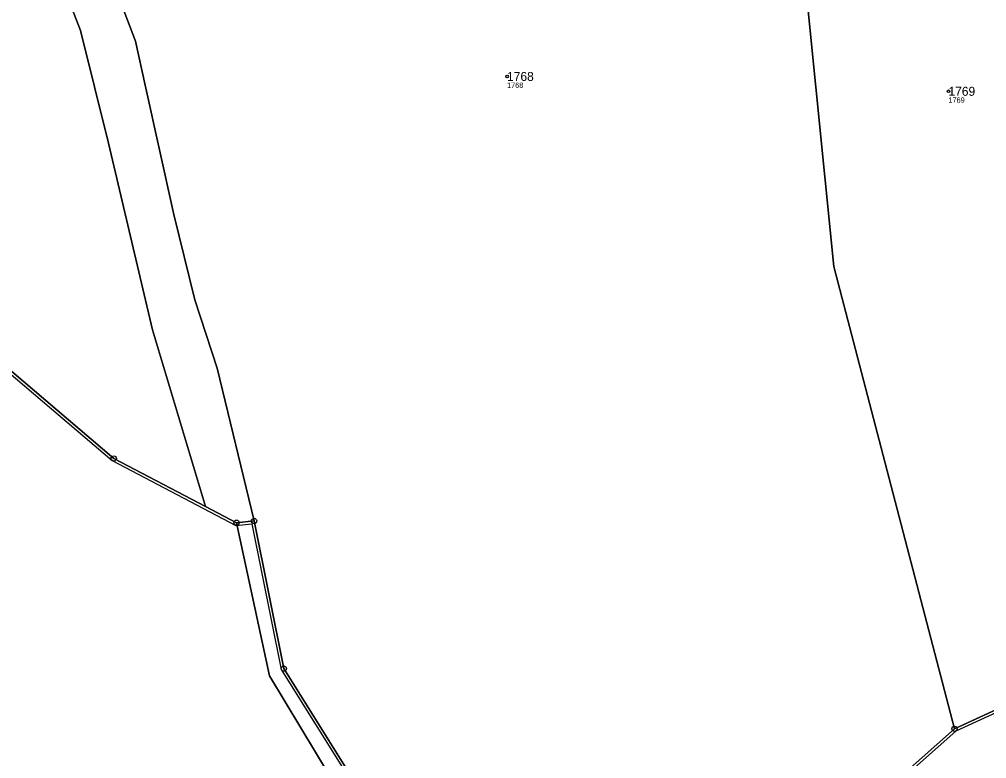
# Model space of a CAD drawing. Extents: x -770088 to -765625, y -1057899 to -1053934.
# Drawn here: x -767729.4 to -767546.4, y -1055752.9 to -1055612.9 of the extents above; entities that cross this region are included whole.
import ezdxf

# ---------------------------------------------------------------- set-up
doc = ezdxf.new("R2010")
doc.units = 0
for name, color, linetype in [('Definiční body', 7, 'Continuous'), ('Hranice parcel', 7, 'Continuous'), ('Parcelní čísla', 7, 'Continuous'), ('Polygon parcely', 7, 'Continuous'), ('Vnitřní kresba', 7, 'Continuous'), ('Značky bodu BP', 7, 'Continuous')]:
    doc.layers.add(name, color=color, linetype=linetype)

msp = doc.modelspace()

# ---------------------------------------------------------------- linework, layer by layer
at = {"layer": 'Definiční body'}
for centre in [(-767637.15, -1055623.73), (-767553.65, -1055626.54)]:
    msp.add_circle(centre, 0.25, dxfattribs=at)
at = {"layer": 'Hranice parcel'}
for p, q in [((-767694.2, -1055705.14), (-767688.33, -1055708.21)), ((-767688.33, -1055708.21), (-767685.01, -1055707.88)), ((-767552.51, -1055747.23), (-767526.88, -1055735.47))]:
    msp.add_line(p, q, dxfattribs=at)
for points in [[(-767685.01, -1055707.88), (-767692, -1055678.93), (-767696.21, -1055666.01), (-767700.19, -1055649.85), (-767705.63, -1055625.36), (-767707.42, -1055617.04), (-767716.16, -1055594.17), (-767721.17, -1055581.35), (-767730.22, -1055558.23), (-767733.29, -1055543.04), (-767733.19, -1055525.38), (-767730.55, -1055514.39), (-767726.52, -1055509.04), (-767726.49, -1055503.44)], [(-767694.2, -1055705.14), (-767704.24, -1055671.7), (-767712.56, -1055636.33), (-767717.83, -1055615.02), (-767726.52, -1055592.58), (-767741.87, -1055564), (-767746.66, -1055553.56), (-767747.75, -1055549.17), (-767748.22, -1055543.05), (-767746.48, -1055522.16), (-767747.15, -1055505.65)], [(-767552.51, -1055747.23), (-767575.32, -1055659.71), (-767588.91, -1055524.49)], [(-767983.52, -1055552.84), (-767912.57, -1055567.84), (-767860.83, -1055579.25), (-767844.82, -1055586.75), (-767796.24, -1055618.55), (-767763.05, -1055652.16), (-767711.56, -1055696.05), (-767694.2, -1055705.14)], [(-767391.2, -1056169.09), (-767417.3, -1056105.71), (-767429.7, -1056093.99), (-767435.73, -1056084.7), (-767495.32, -1056050.14), (-767533.97, -1056040.27), (-767559.59, -1056004.47), (-767572.95, -1055975.44), (-767598.42, -1055931.17), (-767621.41, -1055888.84), (-767634.7, -1055844.52), (-767634.6, -1055821.05), (-767640.38, -1055801.4), (-767667.3, -1055761.84), (-767682.06, -1055737.19), (-767688.33, -1055708.21)], [(-767685.01, -1055707.88), (-767679.38, -1055735.84), (-767665.18, -1055758.55)], [(-767665.18, -1055758.55), (-767656.43, -1055759.95), (-767649.19, -1055772.72), (-767625.46, -1055774.82), (-767583.98, -1055768.27), (-767574.79, -1055766.98), (-767552.51, -1055747.23)]]:
    msp.add_lwpolyline(points, dxfattribs=at)
at = {"layer": 'Polygon parcely'}
for points in [[(-767574.79, -1055766.98), (-767552.51, -1055747.23), (-767575.32, -1055659.71), (-767588.91, -1055524.49), (-767590.45, -1055515.54), (-767624.3, -1055512.63), (-767660.15, -1055509.27), (-767701.59, -1055505.63), (-767726.49, -1055503.44), (-767726.52, -1055509.04), (-767730.55, -1055514.39), (-767733.19, -1055525.38), (-767733.29, -1055543.04), (-767730.22, -1055558.23), (-767721.17, -1055581.35), (-767716.16, -1055594.17), (-767707.42, -1055617.04), (-767705.63, -1055625.36), (-767700.19, -1055649.85), (-767696.21, -1055666.01), (-767692, -1055678.93), (-767685.01, -1055707.88), (-767679.38, -1055735.84), (-767665.18, -1055758.55)], [(-767667.3, -1055761.84), (-767682.06, -1055737.19), (-767688.33, -1055708.21), (-767694.2, -1055705.14), (-767711.56, -1055696.05), (-767763.05, -1055652.16), (-767796.24, -1055618.55), (-767844.82, -1055586.75), (-767860.83, -1055579.25), (-767912.57, -1055567.84), (-767983.52, -1055552.84), (-768086.16, -1055607.62)], [(-767741.87, -1055564), (-767726.52, -1055592.58), (-767717.83, -1055615.02), (-767712.56, -1055636.33), (-767704.24, -1055671.7), (-767694.2, -1055705.14), (-767688.33, -1055708.21), (-767685.01, -1055707.88), (-767692, -1055678.93), (-767696.21, -1055666.01), (-767700.19, -1055649.85), (-767705.63, -1055625.36), (-767707.42, -1055617.04), (-767716.16, -1055594.17), (-767721.17, -1055581.35), (-767730.22, -1055558.23)], [(-767763.05, -1055652.16), (-767711.56, -1055696.05), (-767694.2, -1055705.14), (-767704.24, -1055671.7), (-767712.56, -1055636.33), (-767717.83, -1055615.02), (-767726.52, -1055592.58), (-767741.87, -1055564)], [(-767455.85, -1055702.9), (-767491.49, -1055719.24), (-767492.49, -1055719.7), (-767525.93, -1055735.04), (-767526.88, -1055735.47), (-767552.51, -1055747.23), (-767574.79, -1055766.98)], [(-767685.01, -1055707.88), (-767688.33, -1055708.21), (-767682.06, -1055737.19), (-767667.3, -1055761.84), (-767640.38, -1055801.4), (-767634.6, -1055821.05), (-767634.7, -1055844.52), (-767621.41, -1055888.84), (-767598.42, -1055931.17), (-767572.95, -1055975.44), (-767559.59, -1056004.47), (-767533.97, -1056040.27), (-767495.32, -1056050.14), (-767435.73, -1056084.7), (-767429.7, -1056093.99), (-767417.3, -1056105.71), (-767391.2, -1056169.09)], [(-767569.23, -1055975.4), (-767595.65, -1055929.32), (-767618.1, -1055887.25), (-767630.79, -1055844.75), (-767631.37, -1055821.28), (-767637.99, -1055797.7), (-767665.18, -1055758.55), (-767679.38, -1055735.84), (-767685.01, -1055707.88)]]:
    msp.add_lwpolyline(points, dxfattribs=at)
msp.add_lwpolyline([(-767532.63, -1055628.1), (-767538.38, -1055520.72), (-767588.91, -1055524.49), (-767575.32, -1055659.71), (-767552.51, -1055747.23), (-767526.88, -1055735.47)], close=True, dxfattribs=at)
at = {"layer": 'Vnitřní kresba'}
for p, q in [((-767763.41, -1055652.51), (-767711.83, -1055696.47)), ((-767711.83, -1055696.47), (-767688.43, -1055708.72)), ((-767455.67, -1055703.37), (-767552.25, -1055747.66)), ((-767688.43, -1055708.72), (-767685.41, -1055708.42)), ((-767685.41, -1055708.42), (-767679.85, -1055736.03)), ((-767679.85, -1055736.03), (-767665.48, -1055759.01)), ((-767574.57, -1055767.45), (-767552.25, -1055747.66))]:
    msp.add_line(p, q, dxfattribs=at)
at = {"layer": 'Značky bodu BP'}
for centre, radius in [((-767711.56, -1055696.05), 0.5), ((-767711.56, -1055696.05), 0.0303), ((-767688.33, -1055708.21), 0.5), ((-767688.33, -1055708.21), 0.0303), ((-767685.01, -1055707.88), 0.5), ((-767685.01, -1055707.88), 0.0303), ((-767679.38, -1055735.84), 0.5), ((-767679.38, -1055735.84), 0.0303), ((-767552.51, -1055747.23), 0.5), ((-767552.51, -1055747.23), 0.0303)]:
    msp.add_circle(centre, radius, dxfattribs=at)

# ---------------------------------------------------------------- texts
at = {"layer": 'Definiční body'}
for s, p in [('1768', (-767637.15, -1055625.89)), ('1769', (-767553.65, -1055628.7))]:
    msp.add_text(s, height=1, dxfattribs=at).set_placement(p)
at = {"layer": 'Parcelní čísla'}
for s, p in [('1768', (-767637.15, -1055624.58)), ('1769', (-767553.65, -1055627.39))]:
    msp.add_text(s, height=1.7, dxfattribs=at).set_placement(p)

doc.saveas('drawing.dxf')
